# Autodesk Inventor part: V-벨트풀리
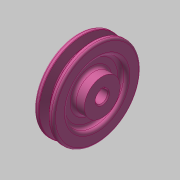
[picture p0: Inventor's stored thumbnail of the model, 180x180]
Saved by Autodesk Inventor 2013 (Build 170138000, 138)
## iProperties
Created: 2020-07
Part Number: V-벨트풀리
Material: 알루미늄 6061
Document SubType Name: Modeling
Designer: mduedu
Density: 2.71 g/cm^3
Mass: 204.727 g
Surface Area: 222.937 cm^2
Volume: 75.5451 cm^3
Author: mduedu
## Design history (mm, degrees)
sketch "스케치1"
  geometry: L1 (-9.5, 0)-(9.5, 0); L2 (9.5, 0)-(9.5, 42.7); L3 (9.5, 42.7)-(-9.5, 42.7); L4 (-9.5, 42.7)-(-9.5, 0); L5 (0, 0)-(0, 42.7); L6 (-4.877, 42.7)-(-1.953, 33.7); L7 (-1.953, 33.7)-(1.953, 33.7); L8 (1.953, 33.7)-(4.877, 42.7); L9 (-9.5, 40)-(9.5, 40); 3 further points
  constraints: 18 end point, 8 point on line, 3 perpendicular, 2 midpoint, 2 parallel, 1 coincident, 1 horizontal, 1 other
  dimensions: "d0" = 85.4 diameter of L3 L1; "d2" = 8 distance of point (4, 40) point (-4, 40); "d3" = 2.7 distance between parallel lines of L9 L3; "d4" = 6.3 distance between parallel lines of L7 L9; "d5" = 36 deg angle of L8 L6; "d6" = 19 distance between parallel lines of L2 L4
revolve "회전1" sketch "스케치1" stored, may be unused: angle "d7" = 90 deg
fillet "모깎기1" dims "d8" = 0.5, "d9" = 1, "d10" = 2
sketch "스케치2"
  geometry: C1 r 17.5 at (0, 0); C2 r 29 at (0, 0); 1 further point
  constraints: 2 centre point, 2 coincident
  dimensions: "d11" = 35 diameter of C1; "d12" = 58 diameter of C2
extrude "돌출1" cut sketch "스케치2" distance "d13" = 6; taper "d14" = 0 deg
fillet "모깎기2" dims "d15" = 3
sketch "스케치3"
  geometry: C1 r 17.5 at (0, 0) reference; 1 further point
extrude "돌출2" join sketch "스케치3" distance "d16" = 5; taper "d17" = 0 deg
sketch "스케치4"
  geometry: L1 (-2, 5.657)-(2, 5.657); L2 (2, 5.657)-(2, 7.8); L3 (2, 7.8)-(-2, 7.8); L4 (-2, 7.8)-(-2, 5.657); A1 r 6 centre (0, 0) between (-2, 5.657) and (2, 5.657); 1 further point
  constraints: 8 end point, 2 parallel, 2 point on circle, 1 centre point, 1 coincident, 1 horizontal, 1 perpendicular
  dimensions: "d18" = 13.8 dimension on A1 L3; "d20" = 12 diameter of A1; "d21" = 4 distance of L2.end L3.end
extrude "돌출3" cut sketch "스케치4" stored distance "d22" = 5; taper "d23" = 0 deg
chamfer "모따기1" distance "d24" = 1; stored, may be unused: second distance "d25" = 2, angle "d26" = 45 deg
sketch "스케치5" dims "d27" = 73
  geometry: C1 r 2.5 at (0, 36.5); 2 further points
  constraints: 2 vertical alignment, 1 centre point, 1 coincident, 2 other
  dimensions: "d28" = 5 diameter of C1
extrude "돌출4" cut sketch "스케치5" distance "d29" = 0.5; taper "d30" = 0 deg
node "솔리드1"
mirror "대칭1"
node "투영된 루프1"
